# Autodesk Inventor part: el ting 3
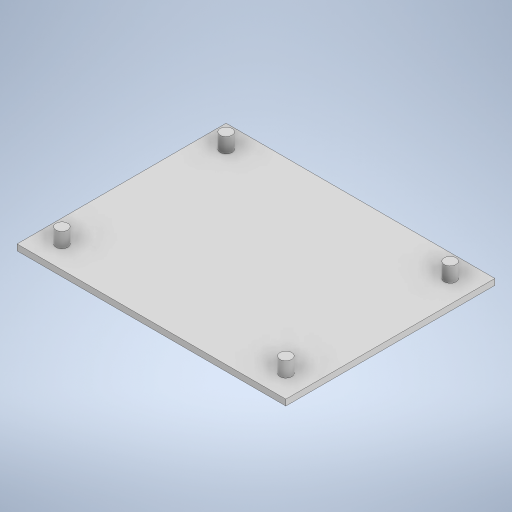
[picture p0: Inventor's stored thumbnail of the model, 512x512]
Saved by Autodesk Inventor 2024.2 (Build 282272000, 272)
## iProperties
Created: 2024-05
Part Number: el ting 3
Material: Generic
Document SubType Name: Modeling
Designer: Karsten
Density: 1 g/cm^3
Appearance: Default
Author: Karsten
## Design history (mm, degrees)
sketch "Sketch1"
  geometry: L1 (0, 0)-(-90, 0); L2 (-90, 0)-(-90, -70); L3 (-90, -70)-(0, -70); L4 (0, -70)-(0, 0)
  constraints: 8 end point, 2 parallel, 1 horizontal, 1 perpendicular
  dimensions: "d0" = 90 distance of L3.end L2.end; "d1" = 70 distance of L2.end L1.end
extrude "Extrusion1" new body sketch "Sketch1" distance "d2" = 2; taper "d3" = 0 deg
sketch "Sketch2"
  geometry: L1 (0, 70)-(0, 0) reference; L2 (0, 70)-(7.5, 70); L3 (90, 70)-(0, 70) reference; L4 (7.5, 70)-(15, 70); L5 (7.5, 70)-(7.5, 62.5); L6 (7.5, 62.5)-(7.5, 7.5); L7 (7.5, 7.5)-(82.5, 7.5); L8 (82.5, 7.5)-(82.5, 62.5); C1 r 2 at (7.5, 62.5); C2 r 2 at (82.5, 62.5); C3 r 2 at (82.5, 7.5); C4 r 2 at (7.5, 7.5)
  constraints: 12 end point, 4 centre point, 4 coincident, 3 perpendicular, 3 point on line
  dimensions: "d4" = 7.5 distance of L1.start L2.end; "d6" = 7.5 distance of L2.end L5.end; "d7" = 55 distance of L5.end L6.end; "d8" = 75 distance of L6.end L7.end; "d9" = 4 diameter of C1; "d10" = 4 diameter of C2; "d11" = 4 diameter of C3; "d12" = 4 diameter of C4
extrude "Extrusion2" join sketch "Sketch2" distance "d13" = 5; taper "d14" = 0 deg
body "Solid1"
